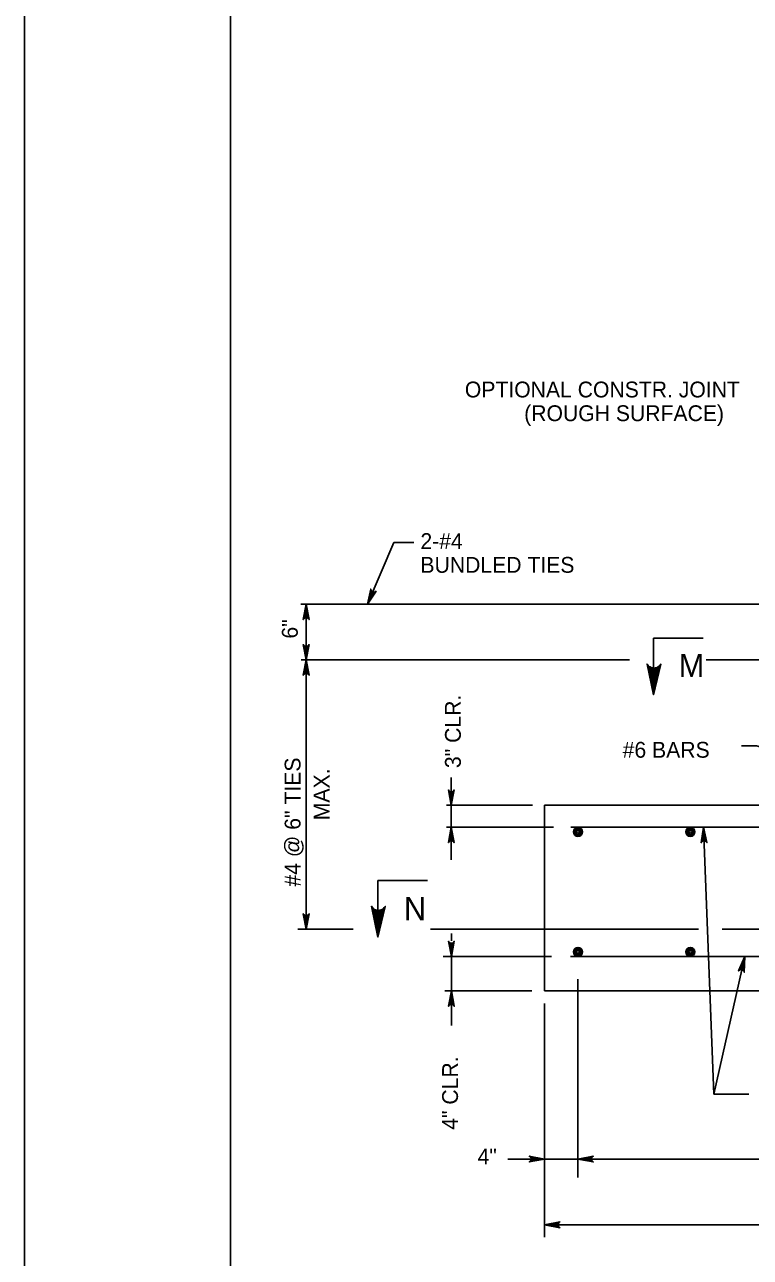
# Model space of a CAD drawing. Extents: x 3475 to 6558, y -3780 to 1166.
# Drawn here: x 3761.3 to 3902.2, y -2257 to -2017.9 of the extents above; entities that cross this region are included whole.
import ezdxf

# ---------------------------------------------------------------- set-up
doc = ezdxf.new("R2010")
doc.units = 0
for name, color, linetype in [('1', 7, 'Continuous'), ('2', 7, 'Continuous'), ('PLT-BNDY', 7, 'Continuous')]:
    doc.layers.add(name, color=color, linetype=linetype)

msp = doc.modelspace()

# ---------------------------------------------------------------- linework, layer by layer
at = {"layer": '1'}
for p, q in [((3827.89, -2130.31), (3833.02, -2118.35)), ((3833.02, -2118.35), (3836.93, -2118.35)), ((3920.33, -2130.31), (3814.96, -2130.31)), ((3816, -2130.31), (3816, -2141.11)), ((3893.08, -2136.88), (3883.43, -2136.88)), ((3883.43, -2147.88), (3883.43, -2136.88)), ((3878.75, -2141.11), (3815.05, -2141.11)), ((3816, -2141.11), (3816, -2193.33)), ((3921.66, -2141.11), (3893.65, -2141.11)), ((3844.17, -2179.87), (3844.17, -2163.93)), ((3859.95, -2169.31), (3843.23, -2169.31)), ((3862.28, -2169.31), (3862.28, -2205.31)), ((3922.57, -2169.31), (3862.28, -2169.31)), ((3864.03, -2173.58), (3843.23, -2173.58)), ((3844.17, -2178.28), (3844.17, -2173.41)), ((3867.4, -2173.58), (4022.74, -2173.58)), ((3895.13, -2225.33), (3893.14, -2173.58)), ((3839.58, -2183.89), (3829.93, -2183.89)), ((3829.93, -2194.89), (3829.93, -2183.89)), ((3825.12, -2193.33), (3814.39, -2193.33)), ((3892.18, -2193.33), (3840.13, -2193.33)), ((3844.19, -2194.18), (3844.19, -2195.61)), ((3921.17, -2193.33), (3896.75, -2193.33)), ((3863.6, -2198.67), (3842.59, -2198.67)), ((3844.19, -2205.31), (3844.19, -2198.67)), ((3867.34, -2198.67), (4022.74, -2198.67)), ((3895.13, -2225.33), (3901.16, -2198.67)), ((3868.76, -2203.06), (3868.76, -2241.53)), ((3859.8, -2205.31), (3842.9, -2205.31)), ((3844.19, -2212.02), (3844.19, -2205.31)), ((4027.86, -2205.31), (3862.28, -2205.31)), ((3862.28, -2207.78), (3862.28, -2253.13)), ((3895.13, -2225.33), (3901.95, -2225.33)), ((4034.57, -2237.94), (3855.14, -2237.94)), ((4027.86, -2250.7), (3862.28, -2250.7))]:
    msp.add_line(p, q, dxfattribs=at)
for points in [[(3827.89, -2130.31), (3828.55, -2127.35), (3828.61, -2127.62), (3828.75, -2127.81), (3828.92, -2127.92), (3829.11, -2127.96), (3829.34, -2127.93), (3829.58, -2127.79), (3827.89, -2130.31), (3829.34, -2127.93), (3829.11, -2127.96), (3827.89, -2130.31), (3828.92, -2127.92), (3828.75, -2127.81), (3827.89, -2130.31), (3828.61, -2127.62)], [(3816, -2130.31), (3816.56, -2133.29), (3816.4, -2133.06), (3816.2, -2132.94), (3816, -2132.91), (3815.8, -2132.94), (3815.6, -2133.06), (3815.44, -2133.29), (3816, -2130.31), (3815.6, -2133.06), (3815.8, -2132.94), (3816, -2130.31), (3816, -2132.91), (3816.2, -2132.94), (3816, -2130.31), (3816.4, -2133.06)], [(3816, -2141.11), (3815.44, -2138.12), (3815.6, -2138.35), (3815.8, -2138.47), (3816, -2138.51), (3816.2, -2138.47), (3816.4, -2138.35), (3816.56, -2138.12), (3816, -2141.11), (3816.4, -2138.35), (3816.2, -2138.47), (3816, -2141.11), (3816, -2138.51), (3815.8, -2138.47), (3816, -2141.11), (3815.6, -2138.35)], [(3816, -2141.11), (3816.56, -2144.09), (3816.4, -2143.86), (3816.2, -2143.74), (3816, -2143.71), (3815.8, -2143.74), (3815.6, -2143.86), (3815.44, -2144.09), (3816, -2141.11), (3815.6, -2143.86), (3815.8, -2143.74), (3816, -2141.11), (3816, -2143.71), (3816.2, -2143.74), (3816, -2141.11), (3816.4, -2143.86)], [(3883.43, -2147.88), (3884.85, -2141.92), (3884.66, -2142.15), (3884.46, -2142.38), (3884.22, -2142.5), (3883.98, -2142.61), (3883.74, -2142.65), (3883.5, -2142.68), (3883.26, -2142.64), (3883.02, -2142.61), (3882.78, -2142.48), (3882.54, -2142.36), (3882.35, -2142.13), (3882.17, -2141.9), (3883.43, -2147.88), (3882.35, -2142.13), (3882.54, -2142.36), (3883.43, -2147.88), (3882.78, -2142.48), (3883.02, -2142.61), (3883.43, -2147.88), (3883.26, -2142.64), (3883.5, -2142.68), (3883.43, -2147.88), (3883.74, -2142.65), (3883.98, -2142.61), (3883.43, -2147.88), (3884.22, -2142.5), (3884.46, -2142.38), (3883.43, -2147.88), (3884.66, -2142.15)], [(3900.53, -2157.76), (3903.44, -2157.76), (3928.08, -2164.71)], [(3844.17, -2169.31), (3843.61, -2166.33), (3843.77, -2166.56), (3843.97, -2166.68), (3844.17, -2166.71), (3844.37, -2166.68), (3844.57, -2166.56), (3844.73, -2166.33), (3844.17, -2169.31), (3844.57, -2166.56), (3844.37, -2166.68), (3844.17, -2169.31), (3844.17, -2166.71), (3843.97, -2166.68), (3844.17, -2169.31), (3843.77, -2166.56)], [(3844.17, -2173.58), (3844.73, -2176.56), (3844.57, -2176.33), (3844.37, -2176.21), (3844.17, -2176.18), (3843.97, -2176.21), (3843.77, -2176.33), (3843.61, -2176.56), (3844.17, -2173.58), (3843.77, -2176.33), (3843.97, -2176.21), (3844.17, -2173.58), (3844.17, -2176.18), (3844.37, -2176.21), (3844.17, -2173.58), (3844.57, -2176.33)], [(3893.14, -2173.58), (3893.81, -2176.53), (3893.73, -2176.42), (3893.65, -2176.31), (3893.54, -2176.26), (3893.44, -2176.2), (3893.34, -2176.19), (3893.24, -2176.17), (3893.14, -2176.2), (3893.04, -2176.22), (3892.94, -2176.28), (3892.85, -2176.34), (3892.77, -2176.46), (3892.7, -2176.58), (3893.14, -2173.58), (3892.77, -2176.46), (3892.85, -2176.34), (3893.14, -2173.58), (3892.94, -2176.28), (3893.04, -2176.22), (3893.14, -2173.58), (3893.14, -2176.2), (3893.24, -2176.17), (3893.14, -2173.58), (3893.34, -2176.19), (3893.44, -2176.2), (3893.14, -2173.58), (3893.54, -2176.26), (3893.65, -2176.31), (3893.14, -2173.58), (3893.73, -2176.42)], [(3816, -2193.33), (3815.44, -2190.35), (3815.6, -2190.58), (3815.8, -2190.7), (3816, -2190.73), (3816.2, -2190.7), (3816.4, -2190.58), (3816.56, -2190.35), (3816, -2193.33), (3816.4, -2190.58), (3816.2, -2190.7), (3816, -2193.33), (3816, -2190.73), (3815.8, -2190.7), (3816, -2193.33), (3815.6, -2190.58)], [(3829.93, -2194.89), (3831.34, -2188.94), (3831.15, -2189.16), (3830.96, -2189.39), (3830.72, -2189.51), (3830.47, -2189.62), (3830.23, -2189.66), (3829.99, -2189.69), (3829.75, -2189.65), (3829.51, -2189.62), (3829.28, -2189.5), (3829.04, -2189.38), (3828.85, -2189.14), (3828.66, -2188.91), (3829.93, -2194.89), (3828.85, -2189.14), (3829.04, -2189.38), (3829.93, -2194.89), (3829.28, -2189.5), (3829.51, -2189.62), (3829.93, -2194.89), (3829.75, -2189.65), (3829.99, -2189.69), (3829.93, -2194.89), (3830.23, -2189.66), (3830.47, -2189.62), (3829.93, -2194.89), (3830.72, -2189.51), (3830.96, -2189.39), (3829.93, -2194.89), (3831.15, -2189.16)], [(3844.19, -2198.67), (3843.63, -2195.69), (3843.79, -2195.92), (3843.99, -2196.03), (3844.19, -2196.07), (3844.39, -2196.03), (3844.59, -2195.92), (3844.75, -2195.69), (3844.19, -2198.67), (3844.59, -2195.92), (3844.39, -2196.03), (3844.19, -2198.67), (3844.19, -2196.07), (3843.99, -2196.03), (3844.19, -2198.67), (3843.79, -2195.92)], [(3901.16, -2198.67), (3901.05, -2201.7), (3900.95, -2201.44), (3900.78, -2201.28), (3900.59, -2201.2), (3900.39, -2201.19), (3900.17, -2201.26), (3899.96, -2201.45), (3901.16, -2198.67), (3900.17, -2201.26), (3900.39, -2201.19), (3901.16, -2198.67), (3900.59, -2201.2), (3900.78, -2201.28), (3901.16, -2198.67), (3900.95, -2201.44)], [(3844.19, -2205.31), (3844.75, -2208.29), (3844.59, -2208.06), (3844.39, -2207.94), (3844.19, -2207.91), (3843.99, -2207.94), (3843.79, -2208.06), (3843.63, -2208.29), (3844.19, -2205.31), (3843.79, -2208.06), (3843.99, -2207.94), (3844.19, -2205.31), (3844.19, -2207.91), (3844.39, -2207.94), (3844.19, -2205.31), (3844.59, -2208.06)], [(3862.28, -2237.94), (3859.3, -2238.5), (3859.53, -2238.34), (3859.65, -2238.14), (3859.68, -2237.94), (3859.65, -2237.74), (3859.53, -2237.54), (3859.3, -2237.39), (3862.28, -2237.94), (3859.53, -2237.54), (3859.65, -2237.74), (3862.28, -2237.94), (3859.68, -2237.94), (3859.65, -2238.14), (3862.28, -2237.94), (3859.53, -2238.34)], [(3868.76, -2237.94), (3871.74, -2237.39), (3871.51, -2237.54), (3871.39, -2237.74), (3871.36, -2237.94), (3871.39, -2238.14), (3871.51, -2238.34), (3871.74, -2238.5), (3868.76, -2237.94), (3871.51, -2238.34), (3871.39, -2238.14), (3868.76, -2237.94), (3871.36, -2237.94), (3871.39, -2237.74), (3868.76, -2237.94), (3871.51, -2237.54)], [(3862.28, -2250.7), (3865.26, -2250.14), (3865.04, -2250.3), (3864.92, -2250.5), (3864.88, -2250.7), (3864.92, -2250.9), (3865.04, -2251.1), (3865.26, -2251.26), (3862.28, -2250.7), (3865.04, -2251.1), (3864.92, -2250.9), (3862.28, -2250.7), (3864.88, -2250.7), (3864.92, -2250.5), (3862.28, -2250.7), (3865.04, -2250.3)]]:
    msp.add_lwpolyline(points, dxfattribs=at)
for centre, radius in [((3868.76, -2174.47), 0.885), ((3868.76, -2174.47), 0.669), ((3890.56, -2174.47), 0.885), ((3890.56, -2174.47), 0.669), ((3868.76, -2174.47), 0.479), ((3868.76, -2174.47), 0.271), ((3890.56, -2174.47), 0.479), ((3890.56, -2174.47), 0.271), ((3868.76, -2197.77), 0.885), ((3868.76, -2197.77), 0.669), ((3868.76, -2197.77), 0.479), ((3868.76, -2197.77), 0.271), ((3890.56, -2197.77), 0.885), ((3890.56, -2197.77), 0.669), ((3890.56, -2197.77), 0.479), ((3890.56, -2197.77), 0.271)]:
    msp.add_circle(centre, radius, dxfattribs=at)
at = {"layer": '2'}
msp.add_line((3801.34, -2383.31), (3801.34, -1819.31), dxfattribs=at)
at = {"layer": 'PLT-BNDY'}
msp.add_lwpolyline([(3761.34, -1804.31), (4602.34, -1804.31), (4602.34, -2398.31), (3761.34, -2398.31)], close=True, dxfattribs=at)

# ---------------------------------------------------------------- texts
at = {"layer": '1'}
for s, height, p in [('OPTIONAL CONSTR. JOINT', 3.072, (3846.8, -2090.18)), ('(ROUGH SURFACE)', 3.072, (3858.32, -2094.78)), ('2-#4', 3.072, (3838.18, -2119.59)), ('BUNDLED TIES', 3.072, (3838.18, -2124.2)), ('M', 4.48, (3888.31, -2144.42)), ('#6 BARS', 3.072, (3877.44, -2160.08)), ('N', 4.48, (3834.96, -2191.6)), ('4"', 3.072, (3849.27, -2238.97))]:
    msp.add_text(s, height=height, dxfattribs=at).set_placement(p)
for s, p in [('6"', (3814.36, -2136.97)), ('3" CLR.', (3846.02, -2162.09)), ('#4 @ 6" TIES', (3814.9, -2185.08)), ('MAX.', (3820.53, -2172.21)), ('4" CLR.', (3845.47, -2232.27))]:
    msp.add_text(s, height=3.072, rotation=90, dxfattribs=at).set_placement(p)

doc.saveas('drawing.dxf')
